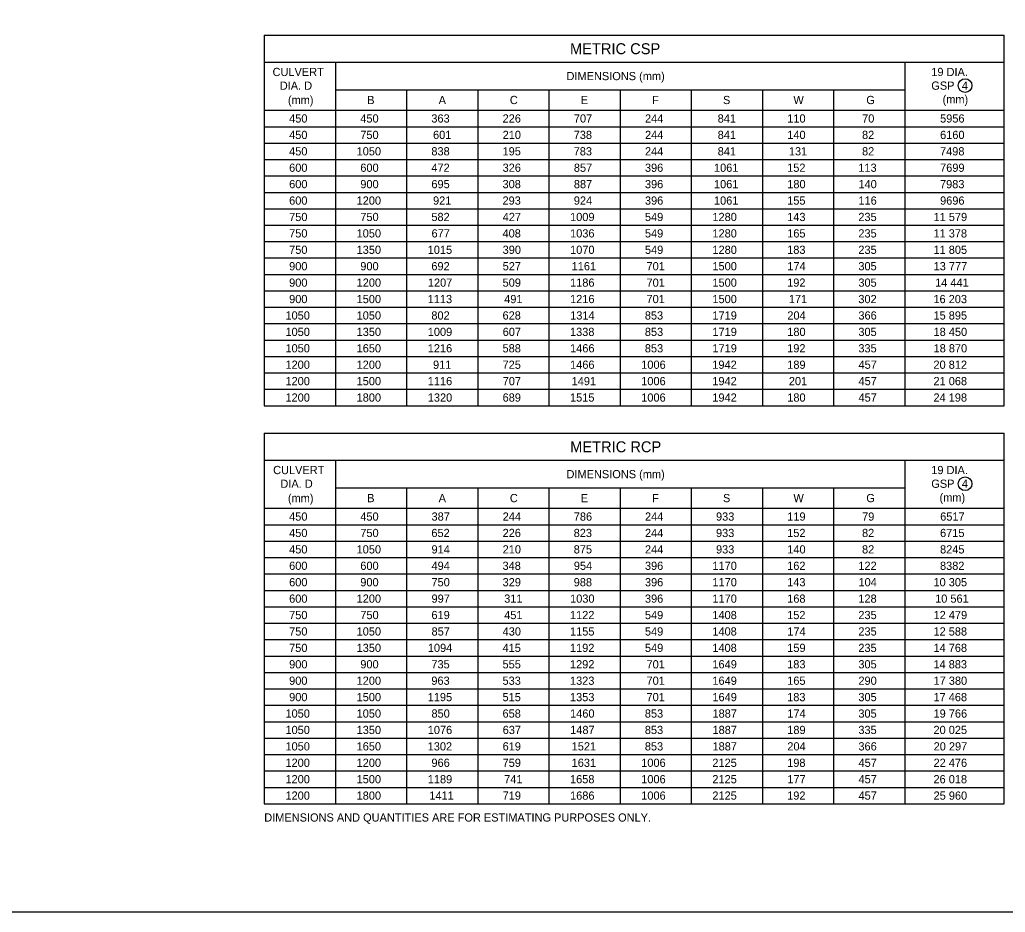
# Model space of a CAD drawing. Extents: x 49991.4 to 50021, y 49987.6 to 50011.4.
# Drawn here: x 50005.52 to 50012.72, y 49987.8 to 49994.32 of the extents above; entities that cross this region are included whole.
import ezdxf

# ---------------------------------------------------------------- set-up
doc = ezdxf.new("R2010")
doc.units = 0
for name, color, linetype in [('Level 1', 7, 'Continuous'), ('Level 2', 7, 'Continuous'), ('Level 3', 7, 'Continuous')]:
    doc.layers.add(name, color=color, linetype=linetype)

msp = doc.modelspace()

# ---------------------------------------------------------------- linework, layer by layer
at = {"layer": 'Level 1'}
msp.add_lwpolyline([(49999.3835, 49998.9992), (50016.7501, 49998.9992), (50016.7501, 49987.7988), (49999.3835, 49987.7988)], close=True, dxfattribs=at)
at = {"layer": 'Level 2'}
for p, q in [((50007.3068, 49994.2119), (50012.7145, 49994.2119)), ((50007.3068, 49994.2119), (50007.3068, 49991.5019)), ((50012.7145, 49991.5019), (50012.7145, 49994.2119)), ((50012.7145, 49994.0119), (50007.3068, 49994.0119)), ((50007.8268, 49994.0119), (50007.8268, 49991.5019)), ((50011.9868, 49994.0119), (50011.9868, 49991.5019)), ((50007.8268, 49993.8119), (50011.9868, 49993.8119)), ((50008.3468, 49993.8119), (50008.3468, 49991.5019)), ((50008.8668, 49993.8119), (50008.8668, 49991.5019)), ((50009.3868, 49993.8119), (50009.3868, 49991.5019)), ((50009.9068, 49993.8119), (50009.9068, 49991.5019)), ((50010.4268, 49993.8119), (50010.4268, 49991.5019)), ((50010.9468, 49993.8119), (50010.9468, 49991.5019)), ((50011.4668, 49993.8119), (50011.4668, 49991.5019)), ((50007.3068, 49993.6619), (50012.7145, 49993.6619)), ((50007.3068, 49993.5419), (50012.7145, 49993.5419)), ((50007.3068, 49993.4219), (50012.7145, 49993.4219)), ((50007.3068, 49993.3019), (50012.7145, 49993.3019)), ((50007.3068, 49993.1819), (50012.7145, 49993.1819)), ((50007.3068, 49993.0619), (50012.7145, 49993.0619)), ((50007.3068, 49992.9419), (50012.7145, 49992.9419)), ((50007.3068, 49992.8219), (50012.7145, 49992.8219)), ((50007.3068, 49992.7019), (50012.7145, 49992.7019)), ((50007.3068, 49992.5819), (50012.7145, 49992.5819)), ((50007.3068, 49992.4619), (50012.7145, 49992.4619)), ((50007.3068, 49992.3419), (50012.7145, 49992.3419)), ((50007.3068, 49992.2219), (50012.7145, 49992.2219)), ((50007.3068, 49992.1019), (50012.7145, 49992.1019)), ((50007.3068, 49991.9819), (50012.7145, 49991.9819)), ((50007.3068, 49991.8619), (50012.7145, 49991.8619)), ((50007.3068, 49991.7419), (50012.7145, 49991.7419)), ((50007.3068, 49991.6219), (50012.7145, 49991.6219)), ((50007.3068, 49991.5019), (50012.7145, 49991.5019)), ((50007.3068, 49991.3019), (50012.7145, 49991.3019)), ((50007.3068, 49991.3019), (50007.3068, 49988.5919)), ((50012.7145, 49988.5919), (50012.7145, 49991.3019)), ((50012.7145, 49991.1019), (50007.3068, 49991.1019)), ((50007.8268, 49991.1019), (50007.8268, 49988.5919)), ((50011.9868, 49991.1019), (50011.9868, 49988.5919)), ((50007.8268, 49990.9019), (50011.9868, 49990.9019)), ((50008.3468, 49990.9019), (50008.3468, 49988.5919)), ((50008.8668, 49990.9019), (50008.8668, 49988.5919)), ((50009.3868, 49990.9019), (50009.3868, 49988.5919)), ((50009.9068, 49990.9019), (50009.9068, 49988.5919)), ((50010.4268, 49990.9019), (50010.4268, 49988.5919)), ((50010.9468, 49990.9019), (50010.9468, 49988.5919)), ((50011.4668, 49990.9019), (50011.4668, 49988.5919)), ((50007.3068, 49990.7519), (50012.7145, 49990.7519)), ((50007.3068, 49990.6319), (50012.7145, 49990.6319)), ((50007.3068, 49990.5119), (50012.7145, 49990.5119)), ((50007.3068, 49990.3919), (50012.7145, 49990.3919)), ((50007.3068, 49990.2719), (50012.7145, 49990.2719)), ((50007.3068, 49990.1519), (50012.7145, 49990.1519)), ((50007.3068, 49990.0319), (50012.7145, 49990.0319)), ((50007.3068, 49989.9119), (50012.7145, 49989.9119)), ((50007.3068, 49989.7919), (50012.7145, 49989.7919)), ((50007.3068, 49989.6719), (50012.7145, 49989.6719)), ((50007.3068, 49989.5519), (50012.7145, 49989.5519)), ((50007.3068, 49989.4319), (50012.7145, 49989.4319)), ((50007.3068, 49989.3119), (50012.7145, 49989.3119)), ((50007.3068, 49989.1919), (50012.7145, 49989.1919)), ((50007.3068, 49989.0719), (50012.7145, 49989.0719)), ((50007.3068, 49988.9519), (50012.7145, 49988.9519)), ((50007.3068, 49988.8319), (50012.7145, 49988.8319)), ((50007.3068, 49988.7119), (50012.7145, 49988.7119)), ((50007.3068, 49988.5919), (50012.7145, 49988.5919))]:
    msp.add_line(p, q, dxfattribs=at)
at = {"layer": 'Level 3'}
for centre in [(50012.4282, 49993.8419), (50012.4282, 49990.9319)]:
    msp.add_circle(centre, 0.05, dxfattribs=at)

# ---------------------------------------------------------------- texts
at = {"layer": 'Level 2'}
for s, height, p in [('METRIC CSP', 0.08, (50009.5409, 49994.0718)), ('CULVERT', 0.06, (50007.3674, 49993.9119)), ('DIMENSIONS (mm)', 0.06, (50009.5154, 49993.8819)), ('19 DIA.', 0.06, (50012.1809, 49993.9119)), ('DIA. D', 0.06, (50007.4203, 49993.8119)), ('GSP', 0.06, (50012.1809, 49993.8119)), ('4', 0.06, (50012.4042, 49993.8119)), ('(mm)', 0.06, (50007.4795, 49993.7069)), ('B', 0.06, (50008.0591, 49993.7069)), ('A', 0.06, (50008.581, 49993.7069)), ('C', 0.06, (50009.1013, 49993.7069)), ('E', 0.06, (50009.6188, 49993.7069)), ('F', 0.06, (50010.1406, 49993.7069)), ('S', 0.06, (50010.659, 49993.7069)), ('W', 0.06, (50011.1735, 49993.7069)), ('G', 0.06, (50011.7061, 49993.7069)), ('(mm)', 0.06, (50012.2634, 49993.7118)), ('450', 0.06, (50007.4886, 49993.5719)), ('450', 0.06, (50008.0086, 49993.5719)), ('363', 0.06, (50008.5277, 49993.5719)), ('226', 0.06, (50009.0484, 49993.5719)), ('707', 0.06, (50009.5691, 49993.5719)), ('244', 0.06, (50010.0889, 49993.5719)), ('841', 0.06, (50010.62, 49993.5719)), ('110', 0.06, (50011.1286, 49993.5719)), ('70', 0.06, (50011.6755, 49993.5719)), ('5956', 0.06, (50012.2453, 49993.5719)), ('450', 0.06, (50007.4886, 49993.4519)), ('750', 0.06, (50008.0086, 49993.4519)), ('601', 0.06, (50008.54, 49993.4519)), ('210', 0.06, (50009.0486, 49993.4519)), ('738', 0.06, (50009.5679, 49993.4519)), ('244', 0.06, (50010.0889, 49993.4519)), ('841', 0.06, (50010.62, 49993.4519)), ('140', 0.06, (50011.1286, 49993.4519)), ('82', 0.06, (50011.6747, 49993.4519)), ('6160', 0.06, (50012.2454, 49993.4519)), ('450', 0.06, (50007.4886, 49993.3319)), ('1050', 0.06, (50007.9816, 49993.3319)), ('838', 0.06, (50008.5279, 49993.3319)), ('195', 0.06, (50009.048, 49993.3319)), ('783', 0.06, (50009.5677, 49993.3319)), ('244', 0.06, (50010.0889, 49993.3319)), ('841', 0.06, (50010.62, 49993.3319)), ('131', 0.06, (50011.14, 49993.3319)), ('82', 0.06, (50011.6747, 49993.3319)), ('7498', 0.06, (50012.2448, 49993.3319)), ('600', 0.06, (50007.4886, 49993.2119)), ('600', 0.06, (50008.0086, 49993.2119)), ('472', 0.06, (50008.5278, 49993.2119)), ('326', 0.06, (50009.0484, 49993.2119)), ('857', 0.06, (50009.5691, 49993.2119)), ('396', 0.06, (50010.0884, 49993.2119)), ('1061', 0.06, (50010.593, 49993.2119)), ('152', 0.06, (50011.1278, 49993.2119)), ('113', 0.06, (50011.6477, 49993.2119)), ('7699', 0.06, (50012.2453, 49993.2119)), ('600', 0.06, (50007.4886, 49993.0919)), ('900', 0.06, (50008.0086, 49993.0919)), ('695', 0.06, (50008.528, 49993.0919)), ('308', 0.06, (50009.0479, 49993.0919)), ('887', 0.06, (50009.5691, 49993.0919)), ('396', 0.06, (50010.0884, 49993.0919)), ('1061', 0.06, (50010.593, 49993.0919)), ('180', 0.06, (50011.1286, 49993.0919)), ('140', 0.06, (50011.6486, 49993.0919)), ('7983', 0.06, (50012.2446, 49993.0919)), ('600', 0.06, (50007.4886, 49992.9719)), ('1200', 0.06, (50007.9816, 49992.9719)), ('921', 0.06, (50008.54, 49992.9719)), ('293', 0.06, (50009.0477, 49992.9719)), ('924', 0.06, (50009.5689, 49992.9719)), ('396', 0.06, (50010.0884, 49992.9719)), ('1061', 0.06, (50010.593, 49992.9719)), ('155', 0.06, (50011.128, 49992.9719)), ('116', 0.06, (50011.6484, 49992.9719)), ('9696', 0.06, (50012.2453, 49992.9719)), ('750', 0.06, (50007.4886, 49992.8519)), ('750', 0.06, (50008.0086, 49992.8519)), ('582', 0.06, (50008.5278, 49992.8519)), ('427', 0.06, (50009.0491, 49992.8519)), ('1009', 0.06, (50009.5415, 49992.8519)), ('549', 0.06, (50010.0884, 49992.8519)), ('1280', 0.06, (50010.5816, 49992.8519)), ('143', 0.06, (50011.1277, 49992.8519)), ('235', 0.06, (50011.648, 49992.8519)), ('11 579', 0.06, (50012.1973, 49992.8519)), ('750', 0.06, (50007.4886, 49992.7319)), ('1050', 0.06, (50007.9816, 49992.7319)), ('677', 0.06, (50008.5291, 49992.7319)), ('408', 0.06, (50009.0479, 49992.7319)), ('1036', 0.06, (50009.5415, 49992.7319)), ('549', 0.06, (50010.0884, 49992.7319)), ('1280', 0.06, (50010.5816, 49992.7319)), ('165', 0.06, (50011.128, 49992.7319)), ('235', 0.06, (50011.648, 49992.7319)), ('11 378', 0.06, (50012.1968, 49992.7319)), ('750', 0.06, (50007.4886, 49992.6119)), ('1350', 0.06, (50007.9816, 49992.6119)), ('1015', 0.06, (50008.5011, 49992.6119)), ('390', 0.06, (50009.0486, 49992.6119)), ('1070', 0.06, (50009.5416, 49992.6119)), ('549', 0.06, (50010.0884, 49992.6119)), ('1280', 0.06, (50010.5816, 49992.6119)), ('183', 0.06, (50011.1277, 49992.6119)), ('235', 0.06, (50011.648, 49992.6119)), ('11 805', 0.06, (50012.1969, 49992.6119)), ('900', 0.06, (50007.4886, 49992.4919)), ('900', 0.06, (50008.0086, 49992.4919)), ('692', 0.06, (50008.5278, 49992.4919)), ('527', 0.06, (50009.0491, 49992.4919)), ('1161', 0.06, (50009.553, 49992.4919)), ('701', 0.06, (50010.1, 49992.4919)), ('1500', 0.06, (50010.5816, 49992.4919)), ('174', 0.06, (50011.1289, 49992.4919)), ('305', 0.06, (50011.648, 49992.4919)), ('13 777', 0.06, (50012.198, 49992.4919)), ('900', 0.06, (50007.4886, 49992.3719)), ('1200', 0.06, (50007.9816, 49992.3719)), ('1207', 0.06, (50008.5022, 49992.3719)), ('509', 0.06, (50009.0484, 49992.3719)), ('1186', 0.06, (50009.5415, 49992.3719)), ('701', 0.06, (50010.1, 49992.3719)), ('1500', 0.06, (50010.5816, 49992.3719)), ('192', 0.06, (50011.1278, 49992.3719)), ('305', 0.06, (50011.648, 49992.3719)), ('14 441', 0.06, (50012.2089, 49992.3719)), ('900', 0.06, (50007.4886, 49992.2519)), ('1500', 0.06, (50007.9816, 49992.2519)), ('1113', 0.06, (50008.5008, 49992.2519)), ('491', 0.06, (50009.06, 49992.2519)), ('1216', 0.06, (50009.5415, 49992.2519)), ('701', 0.06, (50010.1, 49992.2519)), ('1500', 0.06, (50010.5816, 49992.2519)), ('171', 0.06, (50011.14, 49992.2519)), ('302', 0.06, (50011.6478, 49992.2519)), ('16 203', 0.06, (50012.1966, 49992.2519)), ('1050', 0.06, (50007.4616, 49992.1319)), ('1050', 0.06, (50007.9816, 49992.1319)), ('802', 0.06, (50008.5278, 49992.1319)), ('628', 0.06, (50009.0479, 49992.1319)), ('1314', 0.06, (50009.542, 49992.1319)), ('853', 0.06, (50010.0877, 49992.1319)), ('1719', 0.06, (50010.5815, 49992.1319)), ('204', 0.06, (50011.1289, 49992.1319)), ('366', 0.06, (50011.6484, 49992.1319)), ('15 895', 0.06, (50012.1969, 49992.1319)), ('1050', 0.06, (50007.4616, 49992.0119)), ('1350', 0.06, (50007.9816, 49992.0119)), ('1009', 0.06, (50008.5015, 49992.0119)), ('607', 0.06, (50009.0491, 49992.0119)), ('1338', 0.06, (50009.541, 49992.0119)), ('853', 0.06, (50010.0877, 49992.0119)), ('1719', 0.06, (50010.5815, 49992.0119)), ('180', 0.06, (50011.1286, 49992.0119)), ('305', 0.06, (50011.648, 49992.0119)), ('18 450', 0.06, (50012.1975, 49992.0119)), ('1050', 0.06, (50007.4616, 49991.8919)), ('1650', 0.06, (50007.9816, 49991.8919)), ('1216', 0.06, (50008.5015, 49991.8919)), ('588', 0.06, (50009.0479, 49991.8919)), ('1466', 0.06, (50009.5415, 49991.8919)), ('853', 0.06, (50010.0877, 49991.8919)), ('1719', 0.06, (50010.5815, 49991.8919)), ('192', 0.06, (50011.1278, 49991.8919)), ('335', 0.06, (50011.648, 49991.8919)), ('18 870', 0.06, (50012.1975, 49991.8919)), ('1200', 0.06, (50007.4616, 49991.7719)), ('1200', 0.06, (50007.9816, 49991.7719)), ('911', 0.06, (50008.54, 49991.7719)), ('725', 0.06, (50009.048, 49991.7719)), ('1466', 0.06, (50009.5415, 49991.7719)), ('1006', 0.06, (50010.0615, 49991.7719)), ('1942', 0.06, (50010.5808, 49991.7719)), ('189', 0.06, (50011.1284, 49991.7719)), ('457', 0.06, (50011.6491, 49991.7719)), ('20 812', 0.06, (50012.1966, 49991.7719)), ('1200', 0.06, (50007.4616, 49991.6519)), ('1500', 0.06, (50007.9816, 49991.6519)), ('1116', 0.06, (50008.5015, 49991.6519)), ('707', 0.06, (50009.0491, 49991.6519)), ('1491', 0.06, (50009.553, 49991.6519)), ('1006', 0.06, (50010.0615, 49991.6519)), ('1942', 0.06, (50010.5808, 49991.6519)), ('201', 0.06, (50011.14, 49991.6519)), ('457', 0.06, (50011.6491, 49991.6519)), ('21 068', 0.06, (50012.1968, 49991.6519)), ('1200', 0.06, (50007.4616, 49991.5319)), ('1800', 0.06, (50007.9816, 49991.5319)), ('1320', 0.06, (50008.5016, 49991.5319)), ('689', 0.06, (50009.0484, 49991.5319)), ('1515', 0.06, (50009.5411, 49991.5319)), ('1006', 0.06, (50010.0615, 49991.5319)), ('1942', 0.06, (50010.5808, 49991.5319)), ('180', 0.06, (50011.1286, 49991.5319)), ('457', 0.06, (50011.6491, 49991.5319)), ('24 198', 0.06, (50012.1968, 49991.5319)), ('METRIC RCP', 0.08, (50009.5421, 49991.1618)), ('CULVERT', 0.06, (50007.3716, 49991.0019)), ('19 DIA.', 0.06, (50012.1809, 49991.0019)), ('DIMENSIONS (mm)', 0.06, (50009.5154, 49990.9719)), ('DIA. D', 0.06, (50007.4246, 49990.9019)), ('GSP', 0.06, (50012.1809, 49990.9019)), ('4', 0.06, (50012.4042, 49990.9019)), ('(mm)', 0.06, (50007.4796, 49990.7968)), ('B', 0.06, (50008.0591, 49990.7969)), ('A', 0.06, (50008.581, 49990.7969)), ('C', 0.06, (50009.1013, 49990.7969)), ('E', 0.06, (50009.6188, 49990.7969)), ('F', 0.06, (50010.1406, 49990.7969)), ('S', 0.06, (50010.659, 49990.7969)), ('W', 0.06, (50011.1735, 49990.7969)), ('G', 0.06, (50011.7061, 49990.7969)), ('(mm)', 0.06, (50012.2412, 49990.801)), ('450', 0.06, (50007.4886, 49990.6619)), ('450', 0.06, (50008.0086, 49990.6619)), ('387', 0.06, (50008.5291, 49990.6619)), ('244', 0.06, (50009.0489, 49990.6619)), ('786', 0.06, (50009.5684, 49990.6619)), ('244', 0.06, (50010.0889, 49990.6619)), ('933', 0.06, (50010.6077, 49990.6619)), ('119', 0.06, (50011.1284, 49990.6619)), ('79', 0.06, (50011.6754, 49990.6619)), ('6517', 0.06, (50012.246, 49990.6619)), ('450', 0.06, (50007.4886, 49990.5419)), ('750', 0.06, (50008.0086, 49990.5419)), ('652', 0.06, (50008.5278, 49990.5419)), ('226', 0.06, (50009.0484, 49990.5419)), ('823', 0.06, (50009.5677, 49990.5419)), ('244', 0.06, (50010.0889, 49990.5419)), ('933', 0.06, (50010.6077, 49990.5419)), ('152', 0.06, (50011.1278, 49990.5419)), ('82', 0.06, (50011.6747, 49990.5419)), ('6715', 0.06, (50012.2449, 49990.5419)), ('450', 0.06, (50007.4886, 49990.4219)), ('1050', 0.06, (50007.9816, 49990.4219)), ('914', 0.06, (50008.5289, 49990.4219)), ('210', 0.06, (50009.0486, 49990.4219)), ('875', 0.06, (50009.568, 49990.4219)), ('244', 0.06, (50010.0889, 49990.4219)), ('933', 0.06, (50010.6077, 49990.4219)), ('140', 0.06, (50011.1286, 49990.4219)), ('82', 0.06, (50011.6747, 49990.4219)), ('8245', 0.06, (50012.2449, 49990.4219)), ('600', 0.06, (50007.4886, 49990.3019)), ('600', 0.06, (50008.0086, 49990.3019)), ('494', 0.06, (50008.5289, 49990.3019)), ('348', 0.06, (50009.0479, 49990.3019)), ('954', 0.06, (50009.5689, 49990.3019)), ('396', 0.06, (50010.0884, 49990.3019)), ('1170', 0.06, (50010.5816, 49990.3019)), ('162', 0.06, (50011.1278, 49990.3019)), ('122', 0.06, (50011.6478, 49990.3019)), ('8382', 0.06, (50012.2446, 49990.3019)), ('600', 0.06, (50007.4886, 49990.1819)), ('900', 0.06, (50008.0086, 49990.1819)), ('750', 0.06, (50008.5286, 49990.1819)), ('329', 0.06, (50009.0484, 49990.1819)), ('988', 0.06, (50009.5679, 49990.1819)), ('396', 0.06, (50010.0884, 49990.1819)), ('1170', 0.06, (50010.5816, 49990.1819)), ('143', 0.06, (50011.1277, 49990.1819)), ('104', 0.06, (50011.6489, 49990.1819)), ('10 305', 0.06, (50012.1969, 49990.1819)), ('600', 0.06, (50007.4886, 49990.0619)), ('1200', 0.06, (50007.9816, 49990.0619)), ('997', 0.06, (50008.5291, 49990.0619)), ('311', 0.06, (50009.06, 49990.0619)), ('1030', 0.06, (50009.5416, 49990.0619)), ('396', 0.06, (50010.0884, 49990.0619)), ('1170', 0.06, (50010.5816, 49990.0619)), ('168', 0.06, (50011.1279, 49990.0619)), ('128', 0.06, (50011.6479, 49990.0619)), ('10 561', 0.06, (50012.2089, 49990.0619)), ('750', 0.06, (50007.4886, 49989.9419)), ('750', 0.06, (50008.0086, 49989.9419)), ('619', 0.06, (50008.5284, 49989.9419)), ('451', 0.06, (50009.06, 49989.9419)), ('1122', 0.06, (50009.5408, 49989.9419)), ('549', 0.06, (50010.0884, 49989.9419)), ('1408', 0.06, (50010.581, 49989.9419)), ('152', 0.06, (50011.1278, 49989.9419)), ('235', 0.06, (50011.648, 49989.9419)), ('12 479', 0.06, (50012.1973, 49989.9419)), ('750', 0.06, (50007.4886, 49989.8219)), ('1050', 0.06, (50007.9816, 49989.8219)), ('857', 0.06, (50008.5291, 49989.8219)), ('430', 0.06, (50009.0486, 49989.8219)), ('1155', 0.06, (50009.5411, 49989.8219)), ('549', 0.06, (50010.0884, 49989.8219)), ('1408', 0.06, (50010.581, 49989.8219)), ('174', 0.06, (50011.1289, 49989.8219)), ('235', 0.06, (50011.648, 49989.8219)), ('12 588', 0.06, (50012.1968, 49989.8219)), ('750', 0.06, (50007.4886, 49989.7019)), ('1350', 0.06, (50007.9816, 49989.7019)), ('1094', 0.06, (50008.502, 49989.7019)), ('415', 0.06, (50009.048, 49989.7019)), ('1192', 0.06, (50009.5408, 49989.7019)), ('549', 0.06, (50010.0884, 49989.7019)), ('1408', 0.06, (50010.581, 49989.7019)), ('159', 0.06, (50011.1284, 49989.7019)), ('235', 0.06, (50011.648, 49989.7019)), ('14 768', 0.06, (50012.1968, 49989.7019)), ('900', 0.06, (50007.4886, 49989.5819)), ('900', 0.06, (50008.0086, 49989.5819)), ('735', 0.06, (50008.528, 49989.5819)), ('555', 0.06, (50009.048, 49989.5819)), ('1292', 0.06, (50009.5408, 49989.5819)), ('701', 0.06, (50010.1, 49989.5819)), ('1649', 0.06, (50010.5815, 49989.5819)), ('183', 0.06, (50011.1277, 49989.5819)), ('305', 0.06, (50011.648, 49989.5819)), ('14 883', 0.06, (50012.1966, 49989.5819)), ('900', 0.06, (50007.4886, 49989.4619)), ('1200', 0.06, (50007.9816, 49989.4619)), ('963', 0.06, (50008.5277, 49989.4619)), ('533', 0.06, (50009.0477, 49989.4619)), ('1323', 0.06, (50009.5408, 49989.4619)), ('701', 0.06, (50010.1, 49989.4619)), ('1649', 0.06, (50010.5815, 49989.4619)), ('165', 0.06, (50011.128, 49989.4619)), ('290', 0.06, (50011.6486, 49989.4619)), ('17 380', 0.06, (50012.1975, 49989.4619)), ('900', 0.06, (50007.4886, 49989.3419)), ('1500', 0.06, (50007.9816, 49989.3419)), ('1195', 0.06, (50008.5011, 49989.3419)), ('515', 0.06, (50009.048, 49989.3419)), ('1353', 0.06, (50009.5408, 49989.3419)), ('701', 0.06, (50010.1, 49989.3419)), ('1649', 0.06, (50010.5815, 49989.3419)), ('183', 0.06, (50011.1277, 49989.3419)), ('305', 0.06, (50011.648, 49989.3419)), ('17 468', 0.06, (50012.1968, 49989.3419)), ('1050', 0.06, (50007.4616, 49989.2219)), ('1050', 0.06, (50007.9816, 49989.2219)), ('850', 0.06, (50008.5286, 49989.2219)), ('658', 0.06, (50009.0479, 49989.2219)), ('1460', 0.06, (50009.5416, 49989.2219)), ('853', 0.06, (50010.0877, 49989.2219)), ('1887', 0.06, (50010.5822, 49989.2219)), ('174', 0.06, (50011.1289, 49989.2219)), ('305', 0.06, (50011.648, 49989.2219)), ('19 766', 0.06, (50012.1973, 49989.2219)), ('1050', 0.06, (50007.4616, 49989.1019)), ('1350', 0.06, (50007.9816, 49989.1019)), ('1076', 0.06, (50008.5015, 49989.1019)), ('637', 0.06, (50009.0491, 49989.1019)), ('1487', 0.06, (50009.5422, 49989.1019)), ('853', 0.06, (50010.0877, 49989.1019)), ('1887', 0.06, (50010.5822, 49989.1019)), ('189', 0.06, (50011.1284, 49989.1019)), ('335', 0.06, (50011.648, 49989.1019)), ('20 025', 0.06, (50012.1969, 49989.1019)), ('1050', 0.06, (50007.4616, 49988.9819)), ('1650', 0.06, (50007.9816, 49988.9819)), ('1302', 0.06, (50008.5008, 49988.9819)), ('619', 0.06, (50009.0484, 49988.9819)), ('1521', 0.06, (50009.553, 49988.9819)), ('853', 0.06, (50010.0877, 49988.9819)), ('1887', 0.06, (50010.5822, 49988.9819)), ('204', 0.06, (50011.1289, 49988.9819)), ('366', 0.06, (50011.6484, 49988.9819)), ('20 297', 0.06, (50012.198, 49988.9819)), ('1200', 0.06, (50007.4616, 49988.8619)), ('1200', 0.06, (50007.9816, 49988.8619)), ('966', 0.06, (50008.5284, 49988.8619)), ('759', 0.06, (50009.0484, 49988.8619)), ('1631', 0.06, (50009.553, 49988.8619)), ('1006', 0.06, (50010.0615, 49988.8619)), ('2125', 0.06, (50010.5811, 49988.8619)), ('198', 0.06, (50011.1279, 49988.8619)), ('457', 0.06, (50011.6491, 49988.8619)), ('22 476', 0.06, (50012.1973, 49988.8619)), ('1200', 0.06, (50007.4616, 49988.7419)), ('1500', 0.06, (50007.9816, 49988.7419)), ('1189', 0.06, (50008.5015, 49988.7419)), ('741', 0.06, (50009.06, 49988.7419)), ('1658', 0.06, (50009.541, 49988.7419)), ('1006', 0.06, (50010.0615, 49988.7419)), ('2125', 0.06, (50010.5811, 49988.7419)), ('177', 0.06, (50011.1291, 49988.7419)), ('457', 0.06, (50011.6491, 49988.7419)), ('26 018', 0.06, (50012.1968, 49988.7419)), ('1200', 0.06, (50007.4616, 49988.6219)), ('1800', 0.06, (50007.9816, 49988.6219)), ('1411', 0.06, (50008.513, 49988.6219)), ('719', 0.06, (50009.0484, 49988.6219)), ('1686', 0.06, (50009.5415, 49988.6219)), ('1006', 0.06, (50010.0615, 49988.6219)), ('2125', 0.06, (50010.5811, 49988.6219)), ('192', 0.06, (50011.1278, 49988.6219)), ('457', 0.06, (50011.6491, 49988.6219)), ('25 960', 0.06, (50012.1975, 49988.6219)), ('DIMENSIONS AND QUANTITIES ARE FOR ESTIMATING PURPOSES ONLY.', 0.06, (50007.3068, 49988.4619))]:
    msp.add_text(s, height=height, dxfattribs=at).set_placement(p)

doc.saveas('drawing.dxf')
